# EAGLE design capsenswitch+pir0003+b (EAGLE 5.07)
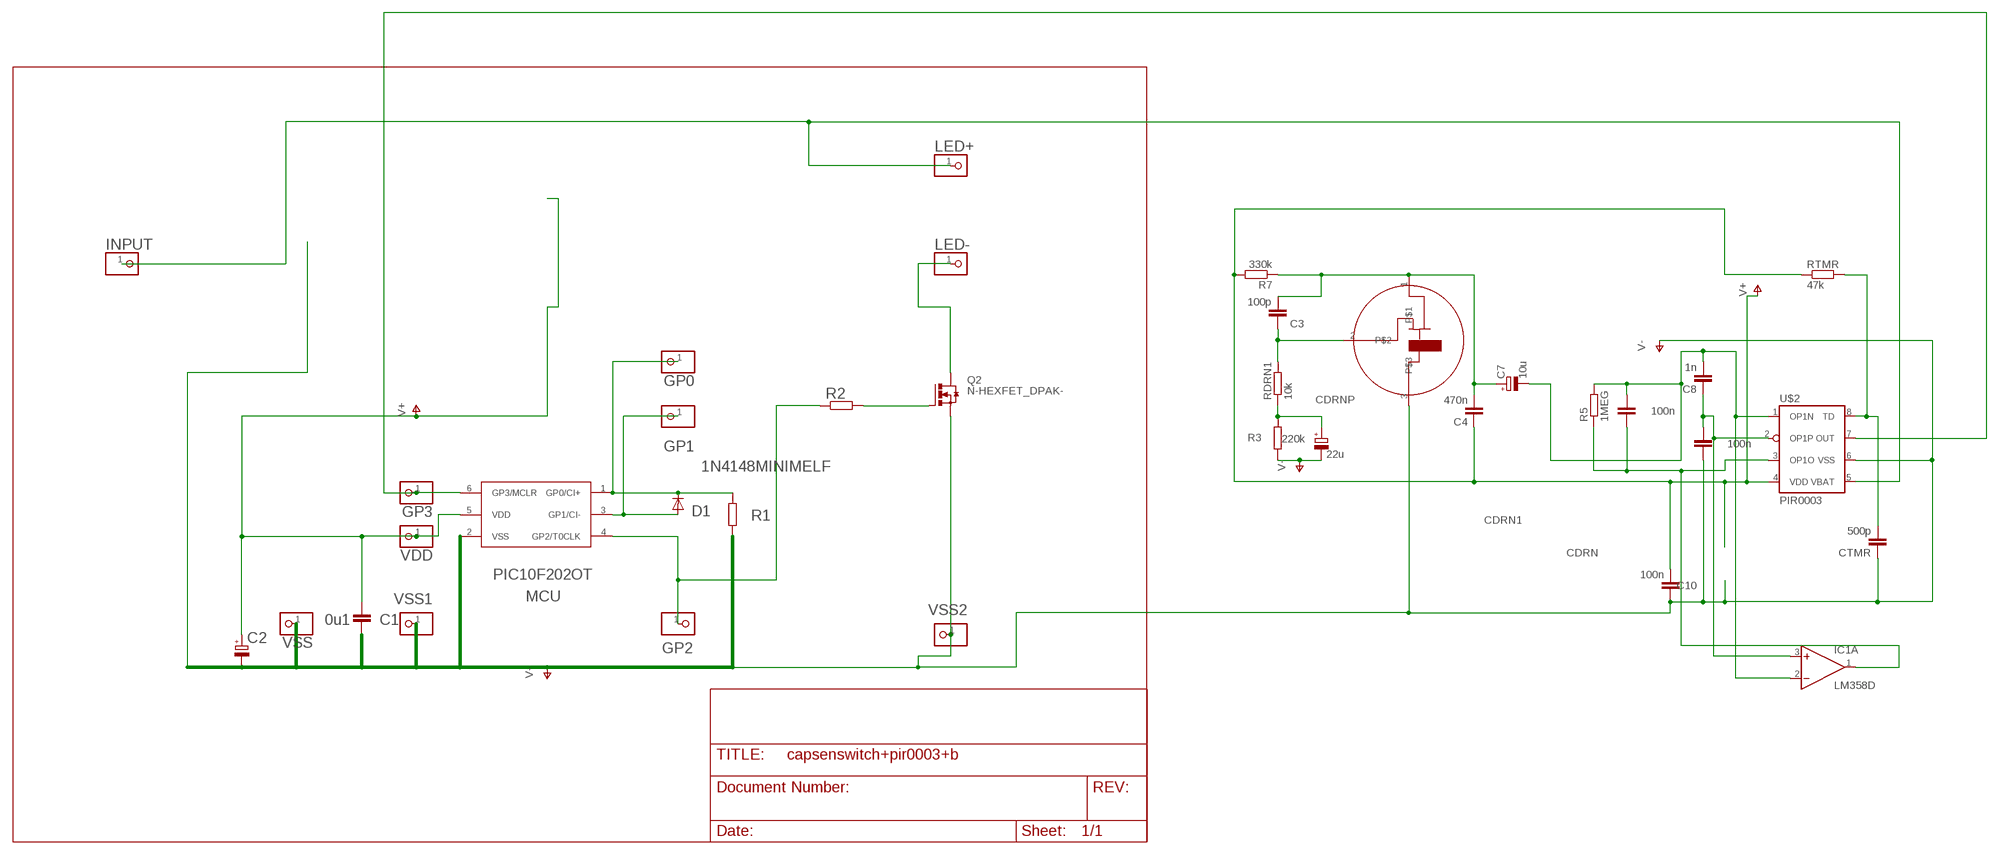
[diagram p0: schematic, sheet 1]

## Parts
C1  0u1  C-EUC1206  [C1206]
C2  CPOL-EUSMCB  [SMC_B]
C3  100p  C-EUC0805  [C0805]
C4  470n  C-EUC0805  [C0805]
C7  10u  CPOL-EUSMCA  [SMC_A]
C8  1n  C-EUC0805  [C0805]
C10  100n  C-EUC1206  [C1206]
CDRN  100n  C-EUC0805  [C0805]
CDRN1  100n  C-EUC0805  [C0805]
CDRNP  22u  CPOL-EUSMCB  [SMC_B]
CTMR  500p  C-EUC0805  [C0805]
D1  1N4148MINIMELF  [MINIMELF]
GP0  PINHD-1X1  [1X01]
GP1  PINHD-1X1  [1X01]
GP2  PINHD-1X1  [1X01]
GP3  PINHD-1X1  [1X01]
IC1  LM358D  [SO08]
INPUT  PINHD-1X1  [1X01]
LED+  PINHD-1X1  [1X01]
LED-  PINHD-1X1  [1X01]
MCU  PIC10F202OT  [SOT23-6]
PIR  RE200B  [R200B]
Q2  N-HEXFET_DPAK-  [TO252]
R1  R-EU_R0805  [R0805]
R2  R-EU_R0805  [R0805]
R3  220k  R-EU_R0805  [R0805]
R5  1MEG  R-EU_R0805  [R0805]
R7  330k  R-EU_R0805  [R0805]
RDRN1  10k  R-EU_R0805  [R0805]
RTMR  47k  R-EU_R0805  [R0805]
U$2  PIR0003  [SO08]
VDD  PINHD-1X1  [1X01]
VSS  PINHD-1X1  [1X01]
VSS1  PINHD-1X1  [1X01]
VSS2  PINHD-1X1  [1X01]

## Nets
GP0: D1.C GP0.1 MCU.1(GP0/CI+) R1.2
GP1: D1.A GP1.1 MCU.3(GP1/CI-)
GP2: GP2.1 MCU.4(GP2/T0CLK) R2.1
GP3: GP3.1 MCU.6(GP3/MCLR) U$2.7(OUT)
HOT: LED-.1 Q2.3(D)
N$1: C3.1 PIR.2 RDRN1.2
N$3: Q2.1(G) R2.2
N$4: C3.2 C4.2 C7.+ PIR.1 R7.1
N$7: CDRNP.+ R3.2 RDRN1.1
N$8: C7.- C8.2 CDRN1.2 IC1.2(A:-IN) R5.2 U$2.1(OP1N)
N$9: C8.1 CDRN.2 IC1.3(A:+IN) U$2.2(OP1P)
N$11: CDRN1.1 IC1.1(A:OUT) R5.1 U$2.3(OP1O)
N$12: CTMR.2 RTMR.2 U$2.8(TD)
V5: INPUT.1 LED+.1 U$2.5(VBAT)
V+: C1.2 C2.+ C4.1 C10.2 MCU.5(VDD) R7.2 RTMR.1 U$2.4(VDD) VDD.1
V-: C1.1 C2.- C10.1 CDRN.1 CDRNP.- CTMR.1 MCU.2(VSS) PIR.3 Q2.2(S) R1.1 R3.1 U$2.6(VSS) VSS1.1 VSS2.1 VSS.1
Unconnected: IC1.5(B:+IN) IC1.6(B:-IN) IC1.7(B:OUT)

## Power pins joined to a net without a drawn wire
V+: IC1.8(P:V+)
V-: IC1.4(P:V-)

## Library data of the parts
C1 C3 C4 C8 C10 CDRN CDRN1 CTMR = rcl:C-EU: CAPACITOR, European symbol
C2 = rcl-2:CPOL-EU: POLARIZED CAPACITOR, European symbol
C7 CDRNP = rcl:CPOL-EU: POLARIZED CAPACITOR, European symbol
D1 = diode-1:1N4148: DIODE
GP0 GP1-GP3 INPUT LED+ LED- VDD VSS VSS1 VSS2 = pinhead(2):PINHD-1X1: PIN HEADER
IC1 = linear:LM358: OP AMP also LM158; LM258; LM2904 Source: http://cache.national.com/ds/LM/LM158.pdf
MCU = microchip-3:PIC10F2*: uPC nW 0,25/0,5k Program Flash memory Comparator
PIR = photo-elements:RE200B
Q2 = transistor-power:N-HEXFET_?-*: HEXFET® Power MOSFET
R1 R2 = rcl-2:R-EU_: RESISTOR, European symbol
R3 R5 R7 RDRN1 RTMR = rcl:R-EU_: RESISTOR, European symbol
U$2 = linear:PIR0003

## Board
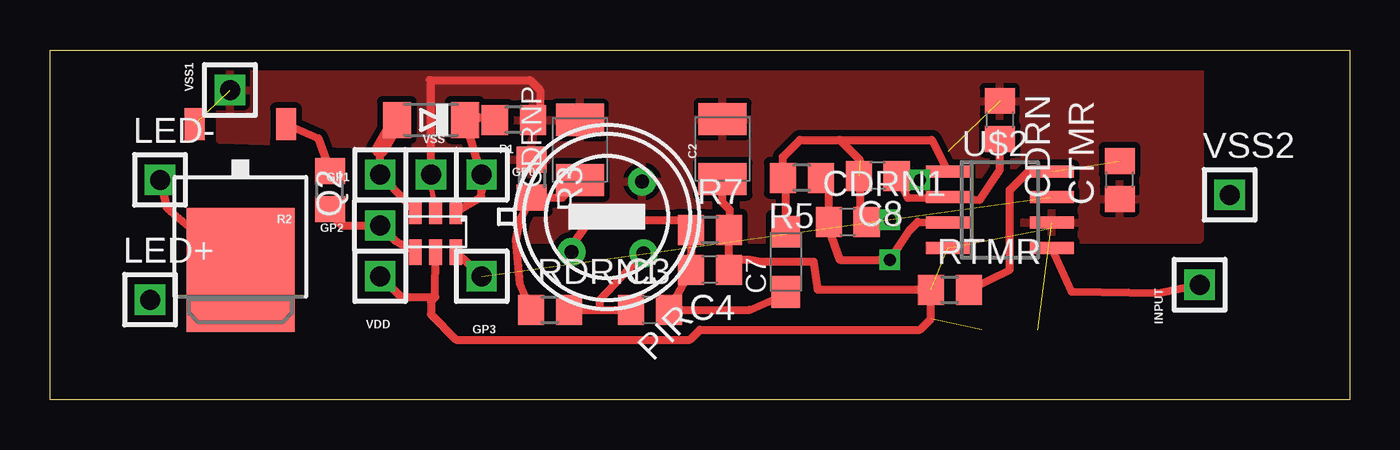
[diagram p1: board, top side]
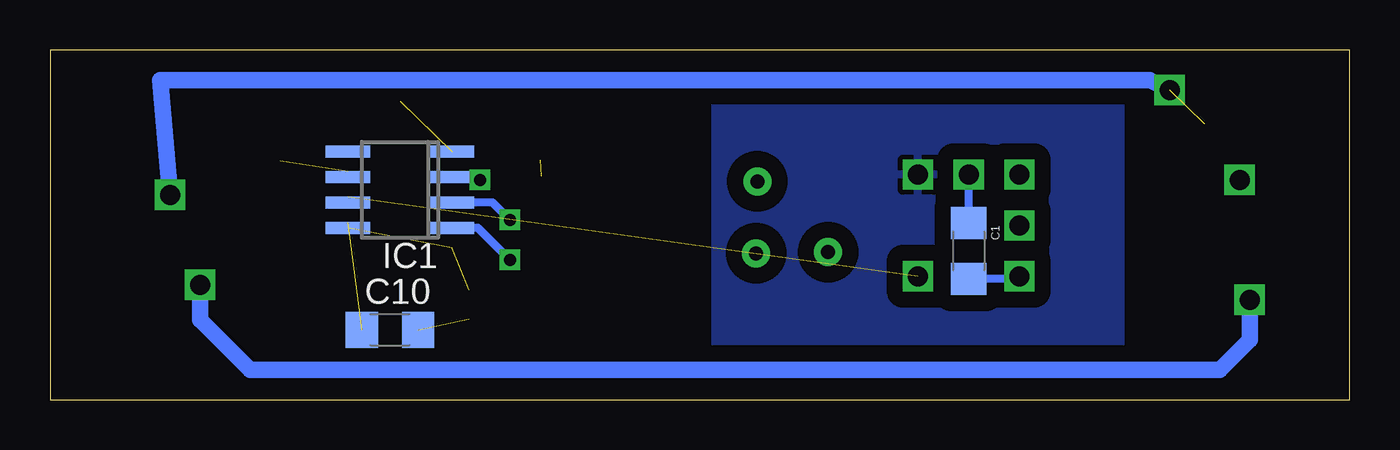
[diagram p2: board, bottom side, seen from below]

Size 65 x 17.5 mm. Coordinates in mm from the lower left corner, seen from the top.
Outline: 0,0 0,17.5 65,17.5 65,0 0,0
Copper layers (1*16): Top 0.035mm / dielectric 1.5mm / Bottom 0.035mm
Design rules "default": minimum track width 10mil, minimum drill 24mil, track to track 8mil, track to pad 8mil, pad to pad 8mil, via to via 8mil, smd to smd 8mil, copper to edge 40mil, drill to drill 8mil, minimum pad ring 10mil, minimum via ring 8mil, stop-mask expansion 4mil, vias tented up to drill 0mil, thermal gap 10mil

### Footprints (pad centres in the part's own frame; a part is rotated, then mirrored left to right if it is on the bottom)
C1206 = smd 1.6 x 1.8: 1 -1.4,0; 2 1.4,0
SMC_B = smd 1.6 x 2.4: + -1.5,0; - 1.5,0
C0805 = smd 1.3 x 1.5: 1 -0.95,0; 2 0.95,0
SMC_A = smd 1.6 x 1.4: + -1.5,0; - 1.5,0
MINIMELF = smd 1.4 x 1.8: A 1.7,0; C -1.7,0
1X01 = drill 1 pad 1.27 square: 1 0,0
SO08 = smd 0.6 x 2.2: 1 -1.905,-2.6; 2 -0.635,-2.6; 3 0.635,-2.6; 4 1.905,-2.6; 5 1.905,2.6; 6 0.635,2.6; 7 -0.635,2.6; 8 -1.905,2.6
SOT23-6 = smd 0.635 x 1.27: 1 -1.016,-1.016; 2 0,-1.016; 3 1.016,-1.016; 4 1.016,1.016; 5 0,1.016; 6 -1.016,1.016
R200B = drill 0.7 pad 1.4 round: 1 -2.5,0; 2 0,-2.58; 3 2.5,0
TO252 = smd 1 x 1.6: 1 -2.28,-3.53; 2 2.28,-3.53 | smd 5.4 x 6.2: 3 0,3.77
R0805 = smd 1.3 x 1.5: 1 -0.95,0; 2 0.95,0

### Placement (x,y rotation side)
C1  19.05,7.45 270 bottom
C2  33.65,12.54 90 top
C3  30,4.5 0 top
C4  33,6.5 180 top
C7  36.8,6.9 90 top
C8  41.4,11.2 180 top
C10  48,3.5 0 bottom
CDRN  47.5,14 270 top
CDRN1  39.9,8.9 0 top
CDRNP  26.5,12.5 90 top
CTMR  53.5,11 90 top
D1  19.05,14 180 top
GP0  21.59,11.26 0 top
GP1  16.51,11.26 0 top
GP2  16.51,8.71 90 top
GP3  21.59,6.17 0 top
IC1  47.5,10.5 90 bottom
INPUT  57.5,5.75 90 top
LED+  5,5 0 top
LED-  5.5,11 0 top
MCU  19.29,8.4 180 top
PIR  27.85,9.15 45 top
Q2  9.53,10.25 180 top
R1  23.2,14 180 top
R2  14,10.5 90 top
R3  24.1,11.06 270 top
R5  37.6,11.1 180 top
R7  33,8.5 0 top
RDRN1  25,4.5 0 top
RTMR  45,5.5 0 top
U$2  47.5,9.5 270 top
VDD  16.51,6.17 0 top
VSS  19.05,11.26 0 top
VSS1  9,15.5 90 top
VSS2  59,10.25 0 top

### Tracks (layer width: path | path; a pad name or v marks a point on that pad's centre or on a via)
GP0
  Top 0.406: MCU.1 21.57,10.15 21.59,10.48 GP0.1 D1.C 21.46,14.11 R1.2
  pour Bottom (isolate 0.813): 11.43,17.14 31.75,17.14 31.75,-0.64 11.43,-0.64
GP1
  Top 0.406: MCU.3 GP1.1 16.51,12.53
  Top 0.813: 16.51,12.53 D1.A
GP2
  Top 0.406: MCU.4 17.29,7.93 GP2.1 14.61,8.71 13.97,9.35 R2.1
GP3  (1 unrouted)
  Top 0.406: MCU.6 GP3.1
HOT
  Top 0.406: LED-.1 5.9,9.54 Q2.3
N$1
  Top 0.406: RDRN1.2 27.5,4.5 | 27.5,4.5 C3.1 | PIR.2 27.5,5 27.5,4.5
N$3
  Top 0.406: R2.2 13.42,13.08 Q2.1
N$4
  Top 0.406: C7.+ 36.8,5.3 35,4.5 C3.2 C4.2 R7.1 31.55,9 27,9 25.88,7.38 PIR.1
N$7
  Top 0.406: RDRN1.1 23.5,5.8 23.3,8 23.5,9 R3.2 25.61,10.11 CDRNP.+
N$8  (via drill 0.6)  (1 unrouted)
  Top 0.406: C7.- 36.8,10.95 R5.2 36.65,12.15 37.5,13 39.5,13 | 39.5,13 40.5,12 40.5,9.25 CDRN1.2 40.95,9 v42,9 | U$2.1 44.1,13 39.5,13
  Bottom 0.406: IC1.2 42.87,9.87 v42,9
N$9  (via drill 0.6)
  Top 0.406: CDRN.2 47.5,11.5 46.5,10 U$2.2 42.9,10.1 C8.1 42.55,11 v43.5,11
  Bottom 0.406: IC1.3 43.63,11.13 v43.5,11
N$11  (via drill 0.6)
  Top 0.406: R5.1 38.95,10.7 CDRN1.1 38.95,8.55 39.5,7 41.5,7 v42,7 43,8.5 43.4,8.9 U$2.3
  Bottom 0.406: IC1.1 43.59,8.6 v42,7
N$12  (1 unrouted)
  Top 0.406: RTMR.2 48,6.5 48,10.5 49,11.5 U$2.8
V5
  Top 0.406: U$2.5 51.1,5.4 55.44,5.31 INPUT.1
  Bottom 0.813: LED+.1 5,3 6.5,1.5 55,1.5 57.5,4 INPUT.1
V+  (3 unrouted)
  Top 0.406: 19.27,5.13 MCU.5 | 19.27,5.13 19.05,4.91 19.05,4.27 20.32,3 32,3 32.5,3.5 43.5,3.5 44.05,4.05 RTMR.1 38.4,5.5 38.2,6.89 35.59,6.89 35,7 34.45,7 C4.1 R7.2 34,8.55 34,9.5 33.65,9.85 C2.+ | 19.27,5.13 17.56,5.13 VDD.1
  Bottom 0.406: C1.2 17.14,6.04 VDD.1
V-  (3 unrouted)
  Top 0.254: MCU.2 19.05,10.62 VSS.1
  Top 0.406: VSS.1 19.05,15.95 19,16 24,16 24.5,15.5 24.5,14.52 R1.1
  Bottom 0.406: C1.1 VSS.1
  Bottom 0.813: VSS2.1 59.5,16 10,16 VSS1.1
  pour Top (isolate 0.305, rank 2): 8.5,13 8.5,16.5 57.5,16.5 57.5,8 23,8 23,12.5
